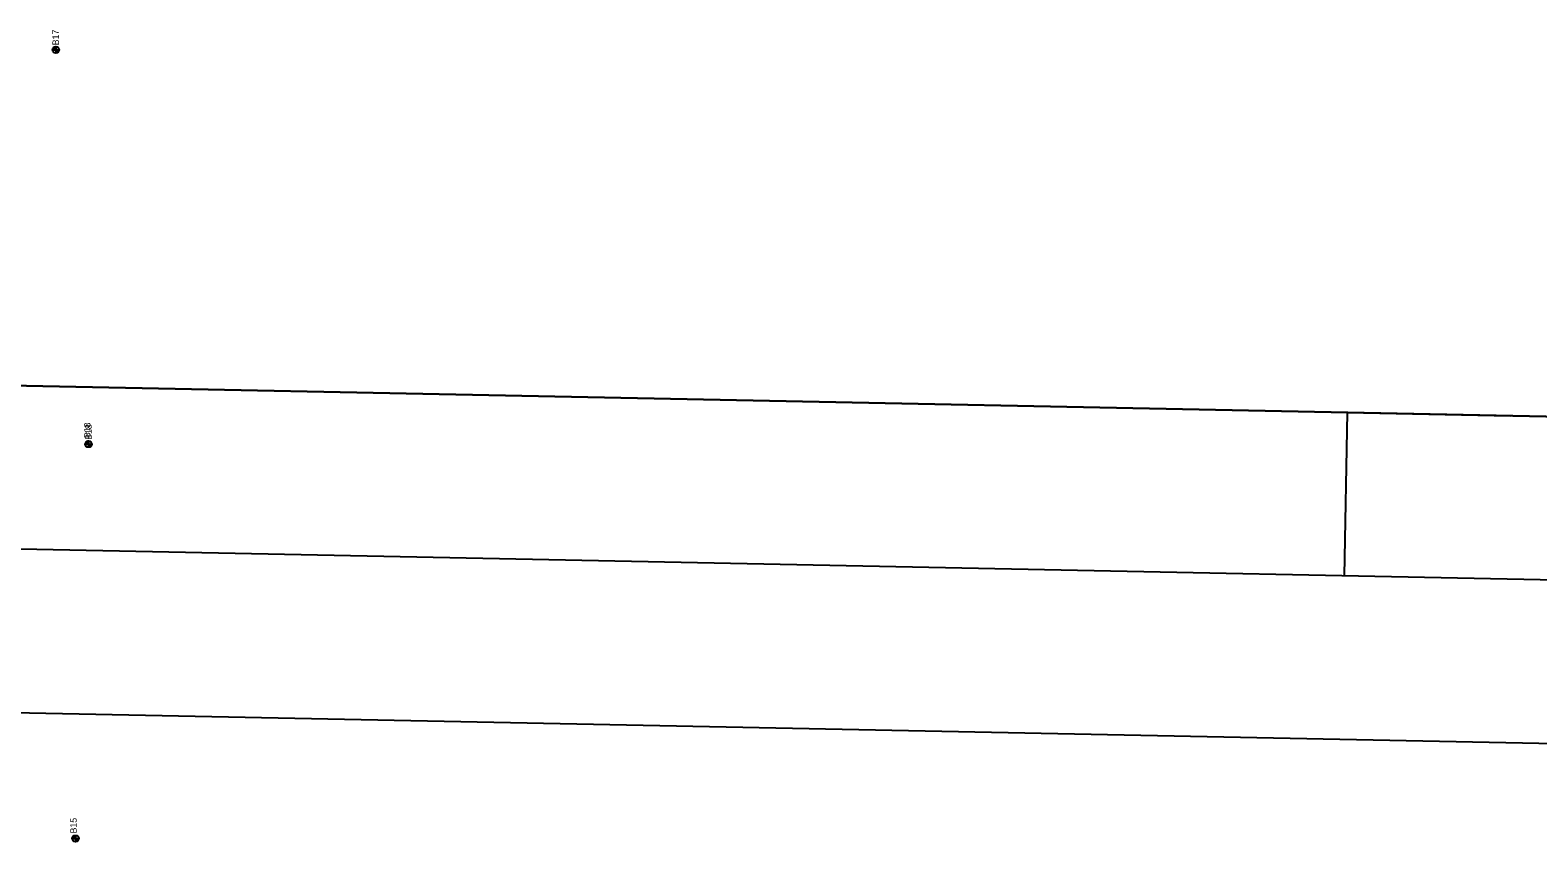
# Model space of a CAD drawing. Extents: x 331323 to 388339, y 121519 to 205315.
# Drawn here: x 361104 to 363413, y 136735 to 137998 of the extents above; entities that cross this region are included whole.
import ezdxf

# ---------------------------------------------------------------- set-up
doc = ezdxf.new("R2010")
doc.units = 0
for name, color, linetype in [('E_SOIL_BORE1 [KAPUR_CADDS_LEVELS]', 7, 'Continuous'), ('E_SOIL_BORE2 [KAPUR_CADDS_LEVELS]', 7, 'Continuous'), ('P_MARK', 7, 'Continuous'), ('P_RDWY_Text', 7, 'Continuous'), ('PLT_Sheet_Border', 7, 'Continuous'), ('PLT_Sheet_Info', 7, 'Continuous')]:
    doc.layers.add(name, color=color, linetype=linetype)

msp = doc.modelspace()

# ---------------------------------------------------------------- linework, layer by layer
at = {"layer": 'P_MARK'}
for p, q in [((361138.1, 137968.3), (361148.1, 137968.3)), ((361143.1, 137973.3), (361143.1, 137963.3)), ((361188.2, 137365.2), (361198.2, 137365.2)), ((361193.2, 137370.2), (361193.2, 137360.2)), ((361168.1, 136761.5), (361178.1, 136761.5)), ((361173.1, 136766.5), (361173.1, 136756.5))]:
    msp.add_line(p, q, dxfattribs=at)
for centre in [(361143.1, 137968.3), (361193.2, 137365.2), (361173.1, 136761.5)]:
    msp.add_circle(centre, 5, dxfattribs=at)
for centre, radius, start, end in [((361143.1, 137968.3), 4.5, 89.9869, 179.9869), ((361143.1, 137968.3), 4, 89.9869, 179.9869), ((361143.1, 137968.3), 3.5, 89.9869, 179.9869), ((361143.1, 137968.3), 3, 89.9869, 179.9869), ((361143.1, 137968.3), 2.5, 89.9869, 179.9869), ((361143.1, 137968.3), 2, 89.9869, 179.9869), ((361143.1, 137968.3), 1.5, 89.9869, 179.9869), ((361143.1, 137968.3), 1, 89.9869, 179.9869), ((361143.1, 137968.3), 0.5, 89.9869, 179.9869), ((361143.1, 137968.3), 4.5, 269.9869, 359.9869), ((361143.1, 137968.3), 4, 269.9869, 359.9869), ((361143.1, 137968.3), 3.5, 269.9869, 359.9869), ((361143.1, 137968.3), 3, 269.9869, 359.9869), ((361143.1, 137968.3), 2.5, 269.9869, 359.9869), ((361143.1, 137968.3), 2, 269.9869, 359.9869), ((361143.1, 137968.3), 1.5, 269.9869, 359.9869), ((361143.1, 137968.3), 1, 269.9869, 359.9869), ((361143.1, 137968.3), 0.5, 269.9869, 359.9869), ((361193.2, 137365.2), 4.5, 89.9869, 179.9869), ((361193.2, 137365.2), 4, 89.9869, 179.9869), ((361193.2, 137365.2), 3.5, 89.9869, 179.9869), ((361193.2, 137365.2), 3, 89.9869, 179.9869), ((361193.2, 137365.2), 2.5, 89.9869, 179.9869), ((361193.2, 137365.2), 2, 89.9869, 179.9869), ((361193.2, 137365.2), 1.5, 89.9869, 179.9869), ((361193.2, 137365.2), 1, 89.9869, 179.9869), ((361193.2, 137365.2), 0.5, 89.9869, 179.9869), ((361193.2, 137365.2), 4.5, 269.9869, 359.9869), ((361193.2, 137365.2), 4, 269.9869, 359.9869), ((361193.2, 137365.2), 3.5, 269.9869, 359.9869), ((361193.2, 137365.2), 3, 269.9869, 359.9869), ((361193.2, 137365.2), 2.5, 269.9869, 359.9869), ((361193.2, 137365.2), 2, 269.9869, 359.9869), ((361193.2, 137365.2), 1.5, 269.9869, 359.9869), ((361193.2, 137365.2), 1, 269.9869, 359.9869), ((361193.2, 137365.2), 0.5, 269.9869, 359.9869), ((361173.1, 136761.5), 4.5, 89.9869, 179.9869), ((361173.1, 136761.5), 4, 89.9869, 179.9869), ((361173.1, 136761.5), 3.5, 89.9869, 179.9869), ((361173.1, 136761.5), 3, 89.9869, 179.9869), ((361173.1, 136761.5), 2.5, 89.9869, 179.9869), ((361173.1, 136761.5), 2, 89.9869, 179.9869), ((361173.1, 136761.5), 1.5, 89.9869, 179.9869), ((361173.1, 136761.5), 1, 89.9869, 179.9869), ((361173.1, 136761.5), 0.5, 89.9869, 179.9869), ((361173.1, 136761.5), 4.5, 269.9869, 359.9869), ((361173.1, 136761.5), 4, 269.9869, 359.9869), ((361173.1, 136761.5), 3.5, 269.9869, 359.9869), ((361173.1, 136761.5), 3, 269.9869, 359.9869), ((361173.1, 136761.5), 2.5, 269.9869, 359.9869), ((361173.1, 136761.5), 2, 269.9869, 359.9869), ((361173.1, 136761.5), 1.5, 269.9869, 359.9869), ((361173.1, 136761.5), 1, 269.9869, 359.9869), ((361173.1, 136761.5), 0.5, 269.9869, 359.9869)]:
    msp.add_arc(centre, radius, start, end, dxfattribs=at)
at = {"layer": 'P_RDWY_Text'}
msp.add_lwpolyline([(354597.6, 137585.1), (371594.2, 137242.8), (371372.7, 126245), (354376.1, 126587.3)], close=True, dxfattribs=at)
at = {"layer": 'PLT_Sheet_Border'}
for points in [[(354376.1, 126587.3), (371372.7, 126245), (371594.2, 137242.8), (354597.6, 137585.1)], [(354501.1, 126834.8), (371047.8, 126501.6), (371259.2, 136999.5), (354712.6, 137332.7)]]:
    msp.add_lwpolyline(points, close=True, dxfattribs=at)
at = {"layer": 'PLT_Sheet_Info'}
for p, q in [((362870.9, 137418.4), (363370.8, 137408.4)), ((363120.8, 137413.4), (363115.8, 137163.5)), ((355219.9, 137072.4), (370966.7, 136755.3))]:
    msp.add_line(p, q, dxfattribs=at)

# ---------------------------------------------------------------- texts
at = {"layer": 'E_SOIL_BORE1 [KAPUR_CADDS_LEVELS]'}
for s, p in [('B17', (361147.9, 137975.3)), ('B18', (361196.2, 137374.2))]:
    msp.add_text(s, height=10, rotation=89.9869, dxfattribs=at).set_placement(p)
at = {"layer": 'E_SOIL_BORE2 [KAPUR_CADDS_LEVELS]'}
for s, p in [('B18', (361198.1, 137371.6)), ('B15', (361175.1, 136769.4))]:
    msp.add_text(s, height=10, rotation=89.9869, dxfattribs=at).set_placement(p)

doc.saveas('drawing.dxf')
